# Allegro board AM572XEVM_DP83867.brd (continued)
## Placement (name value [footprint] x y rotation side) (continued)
R369  47,1%  [402]  36.18 49.88 90 bottom
R370  47,1%  [402]  35.38 46.13 270 bottom
R371  47,1%  [402]  36.98 46.13 270 bottom
R372  47,1%  [402]  40.98 46.13 270 bottom
R373  47,1%  [402]  39.38 44.28 90 bottom
R374  47,1%  [402]  39.38 46.13 270 bottom
R375  47,1%  [402]  38.58 44.28 90 bottom
R376  47,1%  [402]  37.78 49.88 90 bottom
R377  47,1%  [402]  37.78 40.53 270 bottom
R378  47,1%  [402]  38.58 46.13 270 bottom
R379  47,1%  [402]  37.78 44.28 90 bottom
R380  47,1%  [402]  36.18 44.28 90 bottom
R381  47,1%  [402]  36.18 40.53 270 bottom
R382  47,1%  [402]  35.38 44.28 90 bottom
R383  47,1%  [402]  35.38 40.53 270 bottom
R384  0,1%  [402]  24.26 105.41 270 bottom
R385  0,1%  [402]  60.45 2.29 270 bottom
R386  0,1%  [402]  91.19 2.29 270 bottom
R387  0,1%  [402]  63.75 105.41 90 bottom
R391  2.2K,1%  [402]  84.33 81.03 90 top
R392  2.2K,1%  [402]  85.22 81.03 90 top
R393  0,DNI  [402]  89.41 38.35 270 bottom
R394  0,DNI  [402]  90.3 38.35 270 bottom
R395  0,1%  [402]  69.47 53.59 0 top
R396  154K,1%  [402]  115.06 48.77 0 bottom
R397  470K,1%  [402]  115.06 47.88 0 bottom
R398  4.7K  [402]  82.17 85.6 180 top
R399  4.7K  [402]  82.17 84.58 180 top
R400  0,1%  [402]  20.57 3.3 180 bottom
R401  0,1%  [402]  116.59 3.3 0 bottom
R402  0,1%  [402]  20.32 96.27 180 bottom
R403  0,1%  [402]  121.67 89.92 90 bottom
R404  22.6K,1%  [402]  77.22 68.83 270 bottom
R405  10K,DNI  [402]  81.92 68.83 270 bottom
R407  10K,1%  [402]  29.72 105.41 90 bottom
R408  47K,1%  [402]  104.39 8.51 270 bottom
R409  620K  [402]  98.3 6.35 90 bottom
R410  330K  [402]  99.31 6.35 270 bottom
R411  10K,1%,DNI  [402]  67.94 72.77 180 bottom
R412  0,1%  [402]  96.27 8.51 90 bottom
R413  0,1%,DNI  [402]  98.3 8.51 90 bottom
R414  0,1%  [402]  97.28 8.51 270 bottom
R415  47K,1%  [402]  99.31 8.51 270 bottom
R416  0,1%  [402]  87.76 84.45 270 bottom
R417  220,5%  [402]  67.56 35.6 270 bottom
R418  499,1%  [402]  52.07 76.83 180 bottom
R419  10K,1%  [402]  55.25 76.83 0 bottom
R420  40.2K,1%  [402]  49.53 71.75 0 bottom
R421  10K,1%  [402]  73.03 68.33 0 bottom
R422  0,1%  [402]  68.99 49.91 270 bottom
R423  499,1%  [402]  80.52 70.99 0 bottom
R424  10K,1%  [402]  77.72 70.99 0 bottom
R425  40.2K,1%  [402]  81.53 75.82 180 bottom
R429  DNI  [402]  49.53 76.83 180 bottom
R430  DNI  [402]  83.06 70.99 0 bottom
R432  10K,1%,DNI  [402]  117.98 62.99 180 top
R433  10K,1%  [402]  69.85 73.28 45 bottom
R434  10K,1%,DNI  [402]  41.78 69.85 270 bottom
R437  10K,1%  [402]  107.8 54.91 270 top
R440  11K,1%  [402]  88.39 72.26 270 top
R441  11K,1%  [402]  102.16 72.54 270 top
R442  1.87K,1%  [402]  86.18 66.6 90 bottom
R451  0,1%  [402]  101.42 69.19 270 bottom
R461  2.49K,1%  [402]  107.42 62.15 180 bottom
R468  4.7K,0402  [402]  96.49 67.94 270 bottom
R469  4.7K,0402  [402]  110.11 68.24 270 bottom
R470  0,1%  [603]  97.82 61.21 90 top
R471  0,1%  [603]  87.1 73.86 270 top
R472  0,1%  [603]  85.32 73.86 270 top
R473  0,1%  [603]  111.66 74.12 270 top
R474  0,1%  [603]  111.02 60.38 90 top
R475  0,1%  [603]  109.58 74.12 270 top
R476  10K,1%  [402]  82.5 61.93 270 top
R477  0,0402  [402]  87.63 66.98 270 bottom
R478  0,0402  [402]  101.35 66.27 90 bottom
R479  0,0402  [402]  86.64 69.77 270 top
R480  0,0402  [402]  100.41 69.93 270 top
S1  SW PUSH_TH  [SW4_EVQF004R]  31.46 105.32 180 top
S2  SW PUSH_TH  [SW4_EVQF004R]  53.98 2.25 0 top
TP4  TESTPT1  [TP1-8040]  42.55 76.2 0 top
TP5  TP  [TP30C12D]  59.36 83.21 180 bottom
TP6  TP  [TP30C12D]  68.07 26.92 180 bottom
TP7  TP  [TP30C12D]  62.99 85.72 180 bottom
TP8  TP  [TP30C12D]  53.19 64.36 180 bottom
TP9  TP  [TP30C12D]  53.8 63.22 180 bottom
TP13  TP  [TP30C12D]  55.12 71.12 180 bottom
TP16  TP  [TP30C12D]  51.05 45.97 180 bottom
TP17  TP  [TP30C12D]  84.33 78.49 180 bottom
TP18  TP  [TP30C12D]  84.28 76.28 180 bottom
TP19  TP  [TP30C12D]  64.26 59.31 180 bottom
TP20  TP  [TP30C12D]  35.38 51.21 0 top
TP21  TP  [TP30C12D]  35.38 28.8 0 top
TP28  TP  [TP30C12D]  86.31 78.49 0 top
TP29  TP  [TP30C12D]  86.28 76.33 0 top
U1  TPS54531D  [DDA-8]  31.75 65.41 0 top
U2  TPS22965DSG  [WSON-8]  43.18 69.22 180 top
U3  TPS54531D  [DDA-8]  29.34 79.25 0 top
U4  TMP102AIDRLT  [SOT563]  69.34 18.41 90 top
U5  TPS6590376ZWSR  [BGA169_N13_P8]  66.59 72.41 270 top
U6  MCP79410,TFDN  [DFN8_2X3MM]  85.09 84.45 270 top
U7  CDCM9102RHBR  [QFN32]  29.21 50.8 180 top
U8  MEM_24WC256_8SOIC  [SOIC_8]  52.2 81.28 90 bottom
U9  SN74LVC1G11DBV  [SC70-6]  77.47 61.59 0 bottom
U10  SN74LVC1G08DCK  [SC70-5]  80.01 61.59 0 bottom
U11  AM572x  [SKTBGA-ZKK-6334-P760]  67.39 40.81 180 top
U12  TPS_3808G09  [SOT23-6]  58.42 8.89 270 top
U13  TPS_3808G33  [SOT23-6]  51.46 67.34 180 top
U14  DP83867IRRGZ  [QFN48_19-68_280X280_1]  91.25 66.49 270 top
U15  DP83867IRRGZ  [QFN48_19-68_280X280_1]  105 66.79 270 top
U16  TPS74801  [DRC10-11X33]  102.23 38.1 90 bottom
U17  TUSB8041  [VQFN64S9X9P5]  92.71 29.84 90 top
U18  TLV320AIC3104  [QFN32]  58.42 17.78 90 top
U19  TPS77018DBV  [SOT23-5]  58.42 12.7 270 top
U20  SN74LVC2G241  [U_8_DCU]  29.84 36.83 270 top
U21  TPD12S016 24UQFN  [QFN24S_2X4P4]  62.87 95.5 270 top
U22  MEM_MNAND_4GB  [BGA153_P14_P5_11P5X13]  92.08 43.81 180 top
U23  256MBx16 DDR3L  [BGA96_T9_P8_9X14]  41.78 56.41 270 top
U24  256MBx16 DDR3L  [BGA96_T9_P8_9X14]  41.78 45.21 270 top
U25  256MBx16 DDR3L  [BGA96_T9_P8_9X14]  41.78 22.8 270 top
U26  256MBx16 DDR3L  [BGA96_T9_P8_9X14]  41.78 34 270 top
U27  TPS51200_10SON  [DRC10-11X33]  28.58 20.95 90 top
U28  TPS54531D  [DDA-8]  102.87 43.18 0 top
U29  TPS2561DRC  [DRC10-11X33]  102.23 27.94 90 bottom
U30  TPS2561DRC  [DRC10-11X33]  102.23 33.02 90 bottom
U31  PI2DBS212_TQFN  [TQFN28S_3P5X5P5P5]  77.34 76.58 90 top
U32  TL5209  [SO8-25X75]  109.86 48.9 270 bottom
U33  SN75LVCP412A  [QFN20S4X4P5-2]  78.74 84.84 90 top
U34  SN74LVC2G132DCU  [U_8_DCU]  80.01 68.33 180 bottom
U35  TLVH431  [SOT23-3]  50.16 74.3 0 bottom
U42  SN74LVC1G06DCK  [SC70-5]  101.85 8.51 270 bottom
U43  TLVH431  [SOT23-3]  82.42 73.41 180 bottom
U44  SN74LVC1G08  [SM-SO-SC70-5]  109.32 55.42 0 top
U47  TPD1E05U06  [TPD4E05U06DQA]  93.01 74.42 180 top
U48  TPD1E05U06  [TPD4E05U06DQA]  90.02 74.42 180 top
U49  TPD1E05U06  [TPD4E05U06DQA]  106.76 74.7 180 top
U50  TPD1E05U06  [TPD4E05U06DQA]  103.76 74.7 180 top
U51  SN74LVC1G08  [SM-SO-SC70-5]  84.04 62.41 0 top
Y1  CFS-20632768DZBB  [XTAL_CFS-206]  85.09 87.12 270 bottom
Y2  20MHz,SMD  [XTAL2_6X3P5_SMD]  61.4 55.88 180 top
Y3  22.5792MHZ  [XTAL4_3P2X2P5_SMD]  68.96 55.88 0 top
Y5  25MHz  [XTAL_3P2X5SMD]  84.35 68.73 270 top
Y6  DNI  [XTAL_3P2X5SMD]  98.15 69.16 270 top
Y7  24MHz  [OSC4_87-146SMD_126X197-1]  86.61 23.62 270 bottom
Y8  25MHz,8pF  [XTAL4_3P2X2P5_SMD]  29.34 45.09 90 bottom
Y9  16.384MHz  [XTAL4_3P2X2P5_SMD]  74.55 79.88 90 bottom

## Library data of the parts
BAT1 = BATT_HOLD_BH501
C1 C7 C401 = CAP_0.1uF_X7R_25V_10% 0805
C2 C8 C9 C403 C404 C406 C411 C413 = CAP_100UF_TANT_6.3V_3528-21: Tolerance: TOL*; User Part Number: P/N*
C3 C14 C402 C438-C440 C445 = CAP_4.7uF_X5R_50V_10%_LESR_1210: Tolerance: TOL*; User Part Number: P/N*
C4 C13 C408 = CAP_8.2nF_X5R_10V_10%_0201
C5 C10 C409 = CAP
C6 C410 = CAP_6.8nF_X7R_50V_10%_0805
C11 = CAP_820PF_X5R_50V_10%_0805
C12 = CAP_15PF_NPO_50V_5%_0805
C15 C16 C30 C81 C94 C97 C99 C104 C105 C108 C110 C111 C216 C230 C231 C239 C241 C242 C244 C247 C248 C252 C253 C258 C259 C262 C264 C270 C272 C274 C334 C388 C392 C398 C399 C405 C407 C412 C414 C415 C419 C422-C428 C430 C433 C434 C441 C446-C451 = CAP_0.1uF_X7R_16V_10% 0402: signal model: CAP_0.1UF_X7R_16V_10%_0402__402_0.1uf_16V
C17-C22 C24-C29 C63 C80 C92 C246 C255 C256 C267 C496 C500 = CAP_2.2uF_X5R_6.3V_10%_0402
C23 C50 C53 C54 C113 C122 C130 C131 C189 C190 C202 C238 C249 C254 C257 C271 C295 C312 C327 C341 C350 C361 C369 C387 C389 C393-C397 C431 C432 C436 C437 C442 C481 C494 C497 = CAP_10uF_X5R_6.3V_20%_0603
C31 C32 = CAP_10PF_COG_50V_5%_0402
C33 C35 C37 C39 C41 C43 C45 C46 C48 C64 C70 C163 C179 C261 C265 C268 = CAP_4.7uF_X5R_6.3V_20%_0402
C34 C36 C38 C47 C49 C250 C251 = CAP_47uF_X5R_6.3V_20%_1206
C40 C42 C44 C583 C584 = CAP_47uF_X5R_6.3V_20% 0805
C51 C55 C57-C62 C66-C69 C71-C77 C82-C87 C95 C96 C98 C114-C121 C123-C129 C132-C140 C157-C160 C169 C170 C173-C178 C181-C188 C191-C196 C198-C201 C203 C204 C236 C243 C263 C273 C421 C470 C482-C493 C498 C499 = CAP_0.1uF_X5R_6.3V_20% 0201
C52 C56 C78 C88 C89 C161 C162 C165-C168 C171 C172 C266 C269 C275-C294 C296-C311 C313-C326 C328-C333 C335-C340 C342-C349 C351-C360 C362-C368 C370-C386 = CAP_0.22uf_X5R_6.3V_20%_0201
C65 C79 = CAP_0.47UF_X5R_4V_20%_0201
C90 C91 C141-C155 C164 C260 C471 C495 = CAP_1.0UF_X5R_4V_20%_0201
C93 C156 C180 = CAP_22uF_X5R_6.3V_20%_0805
C100-C103 = CAP_18PF_COG_50V_5%_0402
C109 C112 = CAP_220PF_X7R_50V_10%_0402
C197 C237 C245 C390 C391 C429 = CAP_0.001_X7R_50V_10%_0402
C215 = CAP_0.1uF_X7R_16V_10% 0402: User Part Number: P/N*; Tolerance: TOL*; signal model: CAP_0.1UF_X7R_16V_10%_0402__402_0.1uf_16V
C217 C218 C232 C233 = CAP_18PF_NPO_50V_5%_0402
C235 C240 = CAP_33PF_COG_50V_5%_0402
C400 = CAP_10PF_NPO_50V_5%_0402
C416-C418 C420 C454-C457 = CAP_0.1uF_X7R_16V_10% 0402: signal model: CAP_0.1UF_X7R_16V_10%_0402__4_1_0.01uf_16V
C435 = CAP_DNI_0402
C443 = CAP_470PF_X7R_25V_10%_0402
C452 C453 = C_12pF/0402/50V_COG_0402
C472-C476 C478 C586-C593 = CAP_0.1uF_X7R_16V_10% 0402
C479 = CAP_10uF_X5R_6.3V_20%_0603: Tolerance: TOL*; User Part Number: P/N*
C501 C585 = 0.01uFCapacitor16V10%0402
C510-C512 C518-C520 C522 C526 C527 C547 C549-C551 C555 C556 C560-C562 = CAP_0.1uF_X5R_16V_10% 0201
C529-C544 = CAP_4.7pF_C0G_50V_0201
C563-C580 = CAP_1uF_X6S_16V_10% 0402
D1 D2 D24 = DIO_ZEN_DDZ9678-7_1.8V
D3-D7 D41 = LED_LTST_C150GKT
D8-D11 = PROT_PESD0603_240
D12-D19 = IC_TPD1E05U06_0
D20-D23 = IC_TPD2E001DRL
D25-D33 D38 D40 = IC_TPD2EUSB30ADRTR_1: Tolerance: TOL*; User Part Number: P/N*
D34-D37 D42 = IC_TPD1E05U06
F1 = FUSE_4A_QUICK
FB9 = FERRITE_180_800_0805
FL1-FL4 = CHOKE_DLW21SN121HQ2_3: Tolerance: TOL*; User Part Number: P/N*
J1 J5 = HDR_1x1_M_.1
J3 J4 J6 = HDR_1x3_0.1
L1 L2 L16 = INDUCTOR
L3-L5 L9 = IND_PWR_1.0uH_4.2A_SMD
L6-L8 L25 L26 = IND_PWR_1.0uH_2.7A_SMD
L10-L12 L21 L22 L24 = FLT_HIFREQ_.47UF
L13-L15 L17-L20 L23 = FERRITE_220_0805: Tolerance: TOL*; User Part Number: P/N*
MH1-MH5 = TESTPOINT
P1 = CONN_PWRJack_PJ-080BH
P2 P3 = HDR_5x2_M_2.1: User Part Number: ***
P4 = HDR_JTAG_20P
P5 = CONN_RJ45_DUAL_GIGABIT_new
P6 = CONN_11P_eSATA
P7 = CONN_MINI-USB-AB_1
P8 P9 = CONN_STEREO_3.5MM_1SW
P10 = HEADER 6: User Part Number: ***
P11 = HDMI-RA-19_0: Tolerance: TOL; User Part Number: PART#
P12 = microSD_molex_104031-0811: Tolerance: X; User Part Number: X
P13 = CONN_USB3_3.0_A
P15 = CONN_USB3_3.0_A_DUAL
P16-P19 = CONN_30x2_5.27mm: Tolerance: TOL*; User Part Number: PRT#
Q3 Q4 = TRN_DMC56404
Q5 = TRN_NTA4153N
Q6 = TRN_BSS138_0
Q7 = BSS138/SOT_0: Tolerance: TOL*; User Part Number: P/N*
Q8 Q9 = TRN_1: Tolerance: TOL*; User Part Number: P/N*
R1 R7 R34-R36 = RES 0.002_1/2W_1%_0805
R2 R13 R292 = RES_10.1K_1/16W_1%_0402
R3 R5 R9 R14 R294 R296 = RESISTOR
R4 R12 R293 R295 = RES_12.1K_1/16W_1%_0402
R6 R11 R297 = RES_20.5K_1/16W_1%_0402
R8 R240 R273 R274 R303 R328 = RES_1K_1/16W_5%_0402
R10 R20-R24 R26 R27 R31 R37 R41 R42 R44 R46 R49-R52 R56 R58 R180-R183 R187 R188 R190-R197 R200 R205 R214 R236 R239 R247 R248 R260-R265 R272 R285 R287 R288 R313 R320 R321 R330 R335 R405 R407-R411 R415 R419-R421 R424 R425 R429 R430 R432-R434 R437 R476 = RES_10K_1/16W_1%_0402
R15 R33 = RES_4.75K_1/16W_1%_0402
R16 R17 R43 R212 R213 R391 R392 = RES_2.2K_1/16W_1%_0402
R18 R19 R28 R38 R40 R45 R47 R54 R55 R189 R237 R241 R242 R311 R312 R318 R319 R322 R323 = RES_DNI_1/16W_1%_0402
R29 R30 R32 R39 R53 R57 R244 R249 R290 R291 R302 R384 R395 R413 = RES_0_1/16W_1%_0402: signal model: RES_0_1/16W_1%_0402_402_0_1%_0_1%
R48 R219-R222 R286 R298 R309 R310 = RES_100K_1/16W_1%_0402
R59 R62 R66 R204 R207 R209 R215-R218 R243 R245 R246 R333 R334 R398 R399 R468 R469 = RES_4.7K_1/16W_5%_0402
R61 R63 R64 R124-R136 R138-R150 R152 R153 R223 = RES_22_1/16W_5%_0402: signal model: RES_22_1/16W_5%_0402_402_22_5%_22_5%
R68 R69 R97 R98 R396 R397 = RES_470_1/10W_5%_0402
R84-R89 R111-R115 R118 = RES_22_1/16W_5%_0402: signal model: RES_0_1/16W_1%_0402_402_0_1%_0_1%
R201 R442 = RES_1.87K_1/16W_1%_0402
R202 R299 R300 R332 R385-R387 R400-R403 = RES_1M_1/16W_1%_0402
R203 = RES_4.99K_1/16W_1%_0402
R206 = RES_9.09K_1/16W_1%_0402
R210 R211 R314 R315 = RES_27_1/16W_1%_0402
R224 R225 R227 R229 R230 R233 R289 = RES_10_1/10W_5%_0402
R226 R228 R231 R232 R234 R235 R329 = RES_20K_1/16W_1%_0402
R250-R259 = RES_47K_1/16W_1%_0402
R266-R271 = RES_33_1/16W_5%_0402
R275-R278 R418 R423 = RES_240_1/16W_1%_0402
R279-R284 = RES_49.9K_1/16W_1%_0402
R308 = RES_100_1/10W_5%_0402
R331 = RES_1M_1/16W_1%_0402: User Part Number: P/N*; Tolerance: TOL*
R336-R383 = RES_47_1/16W_1%_0402
R393 R394 R412 R414 R416 R422 R451 = RES_0_1/16W_1%_0402
R404 = RES_22.6K_1/16W_1%_0402
R417 = RES_220_1/16W_5%_0402
R440 R441 R477-R480 = RES_11K_1/16W_1%_0402
R461 = RES_2.49K_1/16W_1%_0402
R470-R475 = RES_0_1/16W_1%_0603
S1 S2 = SW PUSH_TH: Tolerance: X; User Part Number: X
TP4 = TESTPT1
TP5-TP9 TP13 TP16-TP21 TP28 TP29 = TP
U1 U3 U28 = IC_TPS54331,3A_0: Tolerance: TOL*; User Part Number: P/N*
U2 = TPS22965DSG_1
U4 = IC_TMP102AIDRL_SOT563
U5 = IC_TPS659039_8
U6 = IC_MCP79410: Tolerance: TOL*; User Part Number: P/N*
U7 = IC_CDCM9102RHBR_0
U8 = MEM_24WC256_0
U9 = IC_SN74LVC1G11_DRY
U10 = IC_SN74LVC1G08_DCK
U11 = IC_AM572x_BGA_36
U12 U13 = PWR_TPS3808G09DBVR_SOT23_0
U14 U15 = DP83867IRRGZ_VQFN48
U16 = PWR_TPS74801_SON: Tolerance: X; User Part Number: X
U17 = IC_TUSB8041_2
U18 = IC_TLV320AIC3104_5
U19 = PWR_TPS7018DBV_SOT23_5
U20 = IC_SN74LVC2G241_1
U21 = IC_TPD12S016
U22 = MEM_MNAND_1
U23-U26 = MEM_DDR3L_256MBx16_0
U27 = IC_TPS51200_10S0N: Tolerance: X; User Part Number: X
U29 U30 = PWR_TPS2560_DRC_0: Tolerance: X; User Part Number: X
U31 = IC_PI2DBS212ZHE_TQFN_9
U32 = PWR_TLV70233DBV_0: Tolerance: X; User Part Number: X
U33 = IC_SN75LVCP412A_1
U34 = IC_SN74LVC2G132DCU
U35 U43 = MA735/TO_0: Tolerance: TOL*; User Part Number: P/N*
U42 = IC_SN74LVC1G06DCK
U44 U51 = SN74LVC1G08DCKT_SC70
U47-U50 = TPD1E05U06
Y1 = CRYS_32_768KHz_SMD
Y2 = CRYS_20MHz_12.5pF_2P_3.2x1.5
Y3 = CRYS_22.5792MHz_7pF_4P_3.2x2.5
Y5 Y6 = CRYS_25MHz_18pF_2P_5.0x3.2
Y7 = CRYS_24MHz_2PIN: Tolerance: TOL*; User Part Number: P/N*
Y8 = CRYS_25MHz_8pF_4P_3.2x2.5
Y9 = CRYS_24MHz_SCC

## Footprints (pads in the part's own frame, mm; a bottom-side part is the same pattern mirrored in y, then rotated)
2XSON
  rect 0.6x0.5 smd: 1(-0.5,0) 2(0.5,0)
201
  custom 0.075x0.075 smd: 1(-0.312,0) 2(0.312,0)
402
  rect 0.45x0.5 smd: 1(-0.475,0) 2(0.475,0)
603
  rect 0.889x0.813 smd: 1(-0.762,0) 2(0.762,0)
805
  rect 1.143x1.27 smd: 1(-0.889,0) 2(0.889,0)
1206
  rect 1.397x1.651 smd: 1(-1.397,0) 2(1.397,0)
1210
  rect 1.6x2.667 smd: 1(-1.397,0) 2(1.397,0)
1812
  rect 1.2x3.3 smd: 1(-1.95,0) 2(1.95,0)
6032
  rect 2.54x2.286 smd: 1(-2.499,0) 2(2.499,0)
BATT2_78X492
  round 1.524 hole 0.965: 1(-2.54,-1.143) 2(2.54,1.143)
BGA96_T9_P8_9X14
  round 0.356 smd: A1(-3.2,6.001) A2(-2.4,6.001) A3(-1.6,6.001) A7(1.6,6.001) A8(2.4,6.001) A9(3.2,6.001) B1(-3.2,5.201) B2(-2.4,5.201) B3(-1.6,5.201) B7(1.6,5.201) B8(2.4,5.201) B9(3.2,5.201) C1(-3.2,4.401) C2(-2.4,4.401) C3(-1.6,4.401) C7(1.6,4.401) C8(2.4,4.401) C9(3.2,4.401) D1(-3.2,3.6) D2(-2.4,3.6) D3(-1.6,3.6) D7(1.6,3.6) D8(2.4,3.6) D9(3.2,3.6) E1(-3.2,2.8) E2(-2.4,2.8) E3(-1.6,2.8) E7(1.6,2.8) E8(2.4,2.8) E9(3.2,2.8) F1(-3.2,2) F2(-2.4,2) F3(-1.6,2) F7(1.6,2) F8(2.4,2) F9(3.2,2) G1(-3.2,1.2) G2(-2.4,1.2) G3(-1.6,1.2) G7(1.6,1.2) G8(2.4,1.2) G9(3.2,1.2) H1(-3.2,0.4) H2(-2.4,0.4) H3(-1.6,0.4) H7(1.6,0.4) H8(2.4,0.4) H9(3.2,0.4) J1(-3.2,-0.4) J2(-2.4,-0.4) J3(-1.6,-0.4) J7(1.6,-0.4) J8(2.4,-0.4) J9(3.2,-0.4) K1(-3.2,-1.2) K2(-2.4,-1.2) K3(-1.6,-1.2) K7(1.6,-1.2) K8(2.4,-1.2) K9(3.2,-1.2) L1(-3.2,-2) L2(-2.4,-2) L3(-1.6,-2) L7(1.6,-2) L8(2.4,-2) L9(3.2,-2) M1(-3.2,-2.8) M2(-2.4,-2.8) M3(-1.6,-2.8) M7(1.6,-2.8) M8(2.4,-2.8) M9(3.2,-2.8) N1(-3.2,-3.6) N2(-2.4,-3.6) N3(-1.6,-3.6) N7(1.6,-3.6) N8(2.4,-3.6) N9(3.2,-3.6) P1(-3.2,-4.401) P2(-2.4,-4.401) P3(-1.6,-4.401) P7(1.6,-4.401) P8(2.4,-4.401) P9(3.2,-4.401) R1(-3.2,-5.201) R2(-2.4,-5.201) R3(-1.6,-5.201) R7(1.6,-5.201) R8(2.4,-5.201) R9(3.2,-5.201) T1(-3.2,-6.001) T2(-2.4,-6.001) T3(-1.6,-6.001) T7(1.6,-6.001) T8(2.4,-6.001) T9(3.2,-6.001)
BGA153_P14_P5_11P5X13
  round 0.254 smd: A1(-3.25,3.25) A2(-2.75,3.25) A3(-2.25,3.25) A4(-1.75,3.25) A5(-1.25,3.25) A6(-0.75,3.25) A7(-0.25,3.25) A8(0.25,3.25) A9(0.75,3.25) A10(1.25,3.25) A11(1.75,3.25) A12(2.25,3.25) A13(2.75,3.25) A14(3.25,3.25) B1(-3.25,2.75) B2(-2.75,2.75) B3(-2.25,2.75) B4(-1.75,2.75) B5(-1.25,2.75) B6(-0.75,2.75) B7(-0.25,2.75) B8(0.25,2.75) B9(0.75,2.75) B10(1.25,2.75) B11(1.75,2.75) B12(2.25,2.75) B13(2.75,2.75) B14(3.25,2.75) C1(-3.25,2.25) C2(-2.75,2.25) C3(-2.25,2.25) C4(-1.75,2.25) C5(-1.25,2.25) C6(-0.75,2.25) C7(-0.25,2.25) C8(0.25,2.25) C9(0.75,2.25) C10(1.25,2.25) C11(1.75,2.25) C12(2.25,2.25) C13(2.75,2.25) C14(3.25,2.25) D1(-3.25,1.75) D2(-2.75,1.75) D3(-2.25,1.75) D4(-1.75,1.75) D12(2.25,1.75) D13(2.75,1.75) D14(3.25,1.75) E1(-3.25,1.25) E2(-2.75,1.25) E3(-2.25,1.25) E5(-1.25,1.25) E6(-0.75,1.25) E7(-0.25,1.25) E8(0.25,1.25) E9(0.75,1.25) E10(1.25,1.25) E12(2.25,1.25) E13(2.75,1.25) E14(3.25,1.25) F1(-3.25,0.75) F2(-2.75,0.75) F3(-2.25,0.75) F5(-1.25,0.75) F10(1.25,0.75) F12(2.25,0.75) F13(2.75,0.75) F14(3.25,0.75) G1(-3.25,0.25) G2(-2.75,0.25) G3(-2.25,0.25) G5(-1.25,0.25) G10(1.25,0.25) G12(2.25,0.25) G13(2.75,0.25) G14(3.25,0.25) H1(-3.25,-0.25) H2(-2.75,-0.25) H3(-2.25,-0.25) H5(-1.25,-0.25) H10(1.25,-0.25) H12(2.25,-0.25) H13(2.75,-0.25) H14(3.25,-0.25) J1(-3.25,-0.75) J2(-2.75,-0.75) J3(-2.25,-0.75) J5(-1.25,-0.75) J10(1.25,-0.75) J12(2.25,-0.75) J13(2.75,-0.75) J14(3.25,-0.75) K1(-3.25,-1.25) K2(-2.75,-1.25) K3(-2.25,-1.25) K5(-1.25,-1.25) K6(-0.75,-1.25) K7(-0.25,-1.25) K8(0.25,-1.25) K9(0.75,-1.25) K10(1.25,-1.25) K12(2.25,-1.25) K13(2.75,-1.25) K14(3.25,-1.25) L1(-3.25,-1.75) L2(-2.75,-1.75) L3(-2.25,-1.75) L12(2.25,-1.75) L13(2.75,-1.75) L14(3.25,-1.75) M1(-3.25,-2.25) M2(-2.75,-2.25) M3(-2.25,-2.25) M4(-1.75,-2.25) M5(-1.25,-2.25) M6(-0.75,-2.25) M7(-0.25,-2.25) M8(0.25,-2.25) M9(0.75,-2.25) M10(1.25,-2.25) M11(1.75,-2.25) M12(2.25,-2.25) M13(2.75,-2.25) M14(3.25,-2.25) N1(-3.25,-2.75) N2(-2.75,-2.75) N3(-2.25,-2.75) N4(-1.75,-2.75) N5(-1.25,-2.75) N6(-0.75,-2.75) N7(-0.25,-2.75) N8(0.25,-2.75) N9(0.75,-2.75) N10(1.25,-2.75) N11(1.75,-2.75) N12(2.25,-2.75) N13(2.75,-2.75) N14(3.25,-2.75) P1(-3.25,-3.25) P2(-2.75,-3.25) P3(-2.25,-3.25) P4(-1.75,-3.25) P5(-1.25,-3.25) P6(-0.75,-3.25) P7(-0.25,-3.25) P8(0.25,-3.25) P9(0.75,-3.25) P10(1.25,-3.25) P11(1.75,-3.25) P12(2.25,-3.25) P13(2.75,-3.25) P14(3.25,-3.25)
BGA169_N13_P8
  round 0.356 smd: A1(-4.8,4.8) A2(-4,4.8) A3(-3.2,4.8) A4(-2.4,4.8) A5(-1.6,4.8) A6(-0.8,4.8) A7(0,4.8) A8(0.8,4.8) A9(1.6,4.8) A10(2.4,4.8) A11(3.2,4.8) A12(4,4.8) A13(4.8,4.8) B1(-4.8,4) B2(-4,4) B3(-3.2,4) B4(-2.4,4) B5(-1.6,4) B6(-0.8,4) B7(0,4) B8(0.8,4) B9(1.6,4) B10(2.4,4) B11(3.2,4) B12(4,4) B13(4.8,4) C1(-4.8,3.2) C2(-4,3.2) C3(-3.2,3.2) C4(-2.4,3.2) C5(-1.6,3.2) C6(-0.8,3.2) C7(0,3.2) C8(0.8,3.2) C9(1.6,3.2) C10(2.4,3.2) C11(3.2,3.2) C12(4,3.2) C13(4.8,3.2) D1(-4.8,2.4) D2(-4,2.4) D3(-3.2,2.4) D4(-2.4,2.4) D5(-1.6,2.4) D6(-0.8,2.4) D7(0,2.4) D8(0.8,2.4) D9(1.6,2.4) D10(2.4,2.4) D11(3.2,2.4) D12(4,2.4) D13(4.8,2.4) E1(-4.8,1.6) E2(-4,1.6) E3(-3.2,1.6) E4(-2.4,1.6) E5(-1.6,1.6) E6(-0.8,1.6) E7(0,1.6) E8(0.8,1.6) E9(1.6,1.6) E10(2.4,1.6) E11(3.2,1.6) E12(4,1.6) E13(4.8,1.6) F1(-4.8,0.8) F2(-4,0.8) F3(-3.2,0.8) F4(-2.4,0.8) F5(-1.6,0.8) F6(-0.8,0.8) F7(0,0.8) F8(0.8,0.8) F9(1.6,0.8) F10(2.4,0.8) F11(3.2,0.8) F12(4,0.8) F13(4.8,0.8) G1(-4.8,0) G2(-4,0) G3(-3.2,0) G4(-2.4,0) G5(-1.6,0) G6(-0.8,0) G7(0,0) G8(0.8,0) G9(1.6,0) G10(2.4,0) G11(3.2,0) G12(4,0) G13(4.8,0) H1(-4.8,-0.8) H2(-4,-0.8) H3(-3.2,-0.8) H4(-2.4,-0.8) H5(-1.6,-0.8) H6(-0.8,-0.8) H7(0,-0.8) H8(0.8,-0.8) H9(1.6,-0.8) H10(2.4,-0.8) H11(3.2,-0.8) H12(4,-0.8) H13(4.8,-0.8) J1(-4.8,-1.6) J2(-4,-1.6) J3(-3.2,-1.6) J4(-2.4,-1.6) J5(-1.6,-1.6) J6(-0.8,-1.6) J7(0,-1.6) J8(0.8,-1.6) J9(1.6,-1.6) J10(2.4,-1.6) J11(3.2,-1.6) J12(4,-1.6) J13(4.8,-1.6) K1(-4.8,-2.4) K2(-4,-2.4) K3(-3.2,-2.4) K4(-2.4,-2.4) K5(-1.6,-2.4) K6(-0.8,-2.4) K7(0,-2.4) K8(0.8,-2.4) K9(1.6,-2.4) K10(2.4,-2.4) K11(3.2,-2.4) K12(4,-2.4) K13(4.8,-2.4) L1(-4.8,-3.2) L2(-4,-3.2) L3(-3.2,-3.2) L4(-2.4,-3.2) L5(-1.6,-3.2) L6(-0.8,-3.2) L7(0,-3.2) L8(0.8,-3.2) L9(1.6,-3.2) L10(2.4,-3.2) L11(3.2,-3.2) L12(4,-3.2) L13(4.8,-3.2) M1(-4.8,-4) M2(-4,-4) M3(-3.2,-4) M4(-2.4,-4) M5(-1.6,-4) M6(-0.8,-4) M7(0,-4) M8(0.8,-4) M9(1.6,-4) M10(2.4,-4) M11(3.2,-4) M12(4,-4) M13(4.8,-4) N1(-4.8,-4.8) N2(-4,-4.8) N3(-3.2,-4.8) N4(-2.4,-4.8) N5(-1.6,-4.8) N6(-0.8,-4.8) N7(0,-4.8) N8(0.8,-4.8) N9(1.6,-4.8) N10(2.4,-4.8) N11(3.2,-4.8) N12(4,-4.8) N13(4.8,-4.8)
CHOKE4_0805-2
  rect 0.65x0.5 smd: 1(-0.8,-0.4) 2(0.8,-0.4) 3(0.8,0.4) 4(-0.8,0.4)
CNPJ-080BH
  round 1.6 hole 1.6 unplated: (0,-11.65)
  rect 2.54x2.54 hole 1.905: 1(0,0)
  oval 2.845x1.448 hole 2.21x0.813: 2(0,-6.65)
  oval 1.448x2.642 hole 0.813x2.007: SHLD1(-5.95,-5.5) SHLD2(5.95,-5.5) SHLD3(-5.95,-10.7) SHLD4(5.95,-10.7)
CON2_49LS
  rect 1.016x1.016 hole 0.508: 1(0,0)
  round 1.016 hole 0.508: 2(0,-1.245)
DDA-8
  rect 2.032x0.635 smd: 1(-2.794,1.905) 2(-2.794,0.635) 3(-2.794,-0.635) 4(-2.794,-1.905) 5(2.794,-1.905) 6(2.794,-0.635) 7(2.794,0.635) 8(2.794,1.905)
  rect 2.362x3.048 smd: 9(0,0)
DFN8_2X3MM
  rect 1.36x1.46 smd: (0,0)
  rect 0.75x0.3 smd: 1(-1.5,0.75) 2(-1.5,0.25) 3(-1.5,-0.25) 4(-1.5,-0.75) 5(1.5,-0.75) 6(1.5,-0.25) 7(1.5,0.25) 8(1.5,0.75)
DO221AC
  rect 1.194x1.499 smd: 1(-2.159,0) 2(2.159,0)
DRC10-11X33
  rect 0.305x0.762 smd: 1(-1.001,-1.473) 2(-0.5,-1.473) 3(0,-1.473) 4(0.5,-1.473) 5(1.001,-1.473) 6(1.001,1.473) 7(0.5,1.473) 8(0,1.473) 9(-0.5,1.473) 10(-1.001,1.473)
  custom 0.406x0.406 smd: 11(0,0)
ESATA-USB_COMBO_RA
  round 1.702 hole 1.702 unplated: (2.13,7.2) (2.13,-7.2)
  round 1.397 hole 0.914: 1(1.905,-3.5) 2(1.905,-1) 3(1.905,1) 4(1.905,3.5)
  oval 1.143x1.016 hole 0.787: 5(0,3.81) 6(0,2.54) 7(0,1.27) 8(0,0) 9(0,-1.27) 10(0,-2.54) 11(0,-3.81)
  oval 2.54x1.524 hole 1.6x0.635: 14(7.73,-9.2) 15(0.53,-9.2) 16(0.53,9.2) 17(7.73,9.2)
FLT3SMD_0805-2
  rect 0.6x0.8 smd: 1(-1,0) 3(1,0)
  rect 0.6x1.9 smd: 2(0,0)
FU250_200X400SMD
  rect 4.318x3.81 smd: 1(-3.188,0) 2(3.188,0)
HDMI-SMT-W-FLANGE
  rect 0.279x1.905 smd: 1(4.75,0) 2(4.249,0) 3(3.749,0) 4(3.249,0) 5(2.748,0) 6(2.248,0) 7(1.748,0) 8(1.247,0) 9(0.747,0) 10(0.246,0) 11(-0.254,0) 12(-0.754,0) 13(-1.255,0) 14(-1.755,0) 15(-2.256,0) 16(-2.756,0) 17(-3.256,0) 18(-3.757,0) 19(-4.257,0)
  oval 1.524x2.286 hole 0.787x1.499: MTG1(-7.239,-1.001) MTG2(7.239,-1.001) MTG3(-7.849,-5.9) MTG4(7.849,-5.9)
HDR2X30SMD_FX18-60P-0P8SV
  round 1.143 hole 1.143 unplated: (-16.325,-2.55) (16.325,2.55)
  rect 0.4x2.1 smd: 1(-11.6,-3.15) 2(-10.8,-3.15) 3(-10,-3.15) 4(-9.2,-3.15) 5(-8.4,-3.15) 6(-7.6,-3.15) 7(-6.8,-3.15) 8(-6,-3.15) 9(-5.2,-3.15) 10(-4.4,-3.15) 11(-3.6,-3.15) 12(-2.8,-3.15) 13(-2,-3.15) 14(-1.2,-3.15) 15(-0.4,-3.15) 16(0.4,-3.15) 17(1.2,-3.15) 18(2,-3.15) 19(2.8,-3.15) 20(3.6,-3.15) 21(4.4,-3.15) 22(5.2,-3.15) 23(6,-3.15) 24(6.8,-3.15) 25(7.6,-3.15) 26(8.4,-3.15) 27(9.2,-3.15) 28(10,-3.15) 29(10.8,-3.15) 30(11.6,-3.15) 31(-11.6,3.15) 32(-10.8,3.15) 33(-10,3.15) 34(-9.2,3.15) 35(-8.4,3.15) 36(-7.6,3.15) 37(-6.8,3.15) 38(-6,3.15) 39(-5.2,3.15) 40(-4.4,3.15) 41(-3.6,3.15) 42(-2.8,3.15) 43(-2,3.15) 44(-1.2,3.15) 45(-0.4,3.15) 46(0.4,3.15) 47(1.2,3.15) 48(2,3.15) 49(2.8,3.15) 50(3.6,3.15) 51(4.4,3.15) 52(5.2,3.15) 53(6,3.15) 54(6.8,3.15) 55(7.6,3.15) 56(8.4,3.15) 57(9.2,3.15) 58(10,3.15) 59(10.8,3.15) 60(11.6,3.15)
  oval 2x3 hole 1x1.8: A2(-16.325,2.55) B1(-13.2,0) B2(13.2,0)
  oval 2x2.4 hole 1x1.2: A3(16.325,-2.55)
HEADER10X2_SMD
  rect 0.711x2.794 smd: 1(-5.715,-2.705) 2(-5.715,2.705) 3(-4.445,-2.705) 4(-4.445,2.705) 5(-3.175,-2.705) 6(-3.175,2.705) 7(-1.905,-2.705) 8(-1.905,2.705) 9(-0.635,-2.705) 10(-0.635,2.705) 11(0.635,-2.705) 12(0.635,2.705) 13(1.905,-2.705) 14(1.905,2.705) 15(3.175,-2.705) 16(3.175,2.705) 17(4.445,-2.705) 18(4.445,2.705) 19(5.715,-2.705) 20(5.715,2.705)
IND130_160X175
  rect 1.651x2.413 smd: 1(-1.651,0) 2(1.651,0)
IND130_208X216
  rect 1.168x4.343 smd: 1(-1.651,0) 2(1.651,0)
IND_0805
  rect 1.27x1.524 smd: 1(-0.97,0) 2(0.97,0)
IND_1008
  rect 0.8x2 smd: 1(-1,0) 2(1,0)
JACK5-472X551-SJ1-3524NG
  round 2.032 hole 1.321: (-2.5,5) (-2.5,-5) (0,5) (0,-5) (5,0)
  oval 2.286x1.524 hole 1.499x0.787: (5,2.5) 2(5,-5) 3(5,5) 4(5,-2.5)
  oval 1.524x2.286 hole 0.787x1.499: 1(0,0)
LED_603
  rect 0.889x0.813 smd: 1(-0.762,0) 2(0.762,0)
MOLEX_104031-0811
  rect 0.75x1.1 smd: 1(3.105,-5.412) 2(2.005,-5.412) 3(0.905,-5.412) 4(-0.195,-5.412) 5(-1.295,-5.412) 6(-2.395,-5.412) 7(-3.495,-5.412) 8(-4.595,-5.412)
  rect 1.2x1 smd: 9(5.748,0.738) 10(5.748,4.438)
  rect 1.55x1.35 smd: 11(5.573,-5.28)
  rect 1.17x1.8 smd: 12(-5.805,-5.062)
  rect 1.9x1.35 smd: 13(-3.722,5.413) 14(2.248,5.413)
MTGH200C102D_PL
  round 4.318 hole 2.591: 1(0,0)
MTGH250C125D_PL
  round 6.35 hole 3.175: 1(0,0)
OSC4_87-146SMD_126X197-1
  rect 1.524x1.27 smd: (-1.854,1.105) (1.854,-1.105) 1(-1.854,-1.105) 2(1.854,1.105)
QFN20S4X4P5-2
  custom 0.058x0.058 smd: 1(-1.9,1) 2(-1.9,0.5) 3(-1.9,0) 4(-1.9,-0.5) 5(-1.9,-1) 6(-1,-1.9) 7(-0.5,-1.9) 8(0,-1.9) 9(0.5,-1.9) 10(1,-1.9) 11(1.9,-1) 12(1.9,-0.5) 13(1.9,0) 14(1.9,0.5) 15(1.9,1) 16(1,1.9) 17(0.5,1.9) 18(0,1.9) 19(-0.5,1.9) 20(-1,1.9)
  rect 2.159x2.159 smd: 21(0,0)
QFN24S_2X4P4
  rect 0.95x0.2 smd: 1(-0.975,1.8) 2(-0.975,1.4) 3(-0.975,1) 4(-0.975,0.6) 5(-0.975,0.2) 6(-0.975,-0.2) 7(-0.975,-0.6) 8(-0.975,-1) 9(-0.975,-1.4) 10(-0.975,-1.8) 13(0.975,-1.8) 14(0.975,-1.4) 15(0.975,-1) 16(0.975,-0.6) 17(0.975,-0.2) 18(0.975,0.2) 19(0.975,0.6) 20(0.975,1) 21(0.975,1.4) 22(0.975,1.8)
  rect 0.2x0.95 smd: 11(-0.2,-1.975) 12(0.2,-1.975) 23(0.2,1.975) 24(-0.2,1.975)
QFN32
  custom 0.058x0.058 smd: 1(-1.75,-2.475) 2(-1.25,-2.475) 3(-0.75,-2.475) 4(-0.25,-2.475) 5(0.25,-2.475) 6(0.75,-2.475) 7(1.25,-2.475) 8(1.75,-2.475) 9(2.475,-1.75) 10(2.475,-1.25) 11(2.475,-0.75) 12(2.475,-0.25) 13(2.475,0.25) 14(2.475,0.75) 15(2.475,1.25) 16(2.475,1.75) 17(1.75,2.475) 18(1.25,2.475) 19(0.75,2.475) 20(0.25,2.475) 21(-0.25,2.475) 22(-0.75,2.475) 23(-1.25,2.475) 24(-1.75,2.475) 25(-2.475,1.75) 26(-2.475,1.25) 27(-2.475,0.75) 28(-2.475,0.25) 29(-2.475,-0.25) 30(-2.475,-0.75) 31(-2.475,-1.25) 32(-2.475,-1.75)
  rect 3.454x3.454 smd: 33(0,0)
QFN48_19-68_280X280_1
  rect 0.813x0.305 smd: 1(-3.5,2.75) 2(-3.5,2.25) 3(-3.5,1.75) 4(-3.5,1.25) 5(-3.5,0.75) 6(-3.5,0.25) 7(-3.5,-0.25) 8(-3.5,-0.75) 9(-3.5,-1.25) 10(-3.5,-1.75) 11(-3.5,-2.25) 12(-3.5,-2.75) 25(3.5,-2.75) 26(3.5,-2.25) 27(3.5,-1.75) 28(3.5,-1.25) 29(3.5,-0.75) 30(3.5,-0.25) 31(3.5,0.25) 32(3.5,0.75) 33(3.5,1.25) 34(3.5,1.75) 35(3.5,2.25) 36(3.5,2.75)
  rect 0.305x0.813 smd: 13(-2.75,-3.5) 14(-2.25,-3.5) 15(-1.75,-3.5) 16(-1.25,-3.5) 17(-0.75,-3.5) 18(-0.25,-3.5) 19(0.25,-3.5) 20(0.75,-3.5) 21(1.25,-3.5) 22(1.75,-3.5) 23(2.25,-3.5) 24(2.75,-3.5) 37(2.75,3.5) 38(2.25,3.5) 39(1.75,3.5) 40(1.25,3.5) 41(0.75,3.5) 42(0.25,3.5) 43(-0.25,3.5) 44(-0.75,3.5) 45(-1.25,3.5) 46(-1.75,3.5) 47(-2.25,3.5) 48(-2.75,3.5)
  rect 5.639x5.639 smd: 49(0,0)
RJ45_2X1_XFRM_LED_NEW
  round 3.251 hole 3.251 unplated: (-6.553,-22.022) (6.553,-22.022)
  round 1.27 hole 0.889: 1(-6.02,-16.764) 2(-4.013,-16.764) 3(-2.007,-16.764) 4(0,-16.764) 5(2.007,-16.764) 6(4.013,-16.764) 7(6.02,-16.764) 8(-5.016,-14.224) 9(-3.01,-14.224) 10(-1.003,-14.224) 11(1.003,-14.224) 12(3.01,-14.224) 13(5.016,-14.224) 14(-6.02,-6.35) 15(-4.013,-6.35) 16(-2.007,-6.35) 17(0,-6.35) 18(2.007,-6.35) 19(4.013,-6.35) 20(6.02,-6.35) 21(-5.016,-3.81) 22(-3.01,-3.81) 23(-1.003,-3.81) 24(1.003,-3.81) 25(3.01,-3.81) 26(5.016,-3.81)
  round 1.397 hole 1.016: 27(-5.944,-24.867) 28(-3.912,-24.867) 29(3.912,-24.867) 30(5.944,-24.867) 31(-5.461,0) 32(-2.921,0) 33(2.921,0) 34(5.461,0)
  round 2.159 hole 1.575: SHLD1(-8.395,-26.594) SHLD2(8.395,-26.594) SHLD3(-8.395,-10.236) SHLD4(8.395,-10.236)
SC70
  rect 0.965x0.813 smd: 1(0,0) 2(0,-1.321) 3(1.778,-0.66)
SC70-5
  rect 0.406x0.762 smd: 1(-0.648,-0.953) 2(0,-0.953) 3(0.648,-0.953) 4(0.648,0.953) 5(-0.648,0.953)
SC70-6
  rect 0.406x0.762 smd: 1(-0.648,-0.953) 2(0,-0.953) 3(0.648,-0.953) 4(0.648,0.953) 5(0,0.953) 6(-0.648,0.953)
SC75
  rect 0.508x0.356 smd: 1(-0.647,0.5) 2(-0.647,-0.5) 3(0.647,0)
SIP2
  rect 1.524x1.524 hole 0.965: 1(0,0)
  round 1.524 hole 0.965: 2(0,-2.54)
SIP3
  rect 1.524x1.524 hole 0.965: 1(0,0)
  round 1.524 hole 0.965: 2(0,-2.54) 3(0,-5.08)
SIP6
  rect 1.524x1.524 hole 0.965: 1(0,0)
  round 1.524 hole 0.965: 2(0,-2.54) 3(0,-5.08) 4(0,-7.62) 5(0,-10.16) 6(0,-12.7)
SKTBGA-ZKK-6334-P760
  round 0.356 smd: A1(-10.8,10.8) A2(-10,10.8) A3(-9.2,10.8) A4(-8.4,10.8) A5(-7.6,10.8) A6(-6.8,10.8) A7(-6,10.8) A8(-5.2,10.8) A9(-4.4,10.8) A10(-3.6,10.8) A11(-2.8,10.8) A12(-2,10.8) A13(-1.2,10.8) A14(-0.4,10.8) A15(0.4,10.8) A16(1.2,10.8) A17(2,10.8) A18(2.8,10.8) A19(3.6,10.8) A20(4.4,10.8) A21(5.2,10.8) A22(6,10.8) A23(6.8,10.8) A24(7.6,10.8) A25(8.4,10.8) A26(9.2,10.8) A27(10,10.8) A28(10.8,10.8) AA1(-10.8,-5.2) AA2(-10,-5.2) AA3(-9.2,-5.2) AA4(-8.4,-5.2) AA5(-7.6,-5.2) AA6(-6.8,-5.2) AA7(-6,-5.2) AA8(-5.2,-5.2) AA9(-4.4,-5.2) AA10(-3.6,-5.2) AA11(-2.8,-5.2) AA12(-2,-5.2) AA13(-1.2,-5.2) AA14(-0.4,-5.2) AA15(0.4,-5.2) AA16(1.2,-5.2) AA17(2,-5.2) AA18(2.8,-5.2) AA19(3.6,-5.2) AA20(4.4,-5.2) AA21(5.2,-5.2) AA22(6,-5.2) AA23(6.8,-5.2) AA24(7.6,-5.2) AA25(8.4,-5.2) AA26(9.2,-5.2) AA27(10,-5.2) AA28(10.8,-5.2) AB1(-10.8,-6) AB2(-10,-6) AB3(-9.2,-6) AB4(-8.4,-6) AB5(-7.6,-6) AB6(-6.8,-6) AB7(-6,-6) AB8(-5.2,-6) AB9(-4.4,-6) AB10(-3.6,-6) AB11(-2.8,-6) AB12(-2,-6) AB13(-1.2,-6) AB14(-0.4,-6) AB15(0.4,-6) AB16(1.2,-6) AB17(2,-6) AB18(2.8,-6) AB19(3.6,-6) AB20(4.4,-6) AB21(5.2,-6) AB22(6,-6) AB23(6.8,-6) AB24(7.6,-6) AB25(8.4,-6) AB27(10,-6) AB28(10.8,-6) AC1(-10.8,-6.8) AC2(-10,-6.8) AC3(-9.2,-6.8) AC4(-8.4,-6.8) AC5(-7.6,-6.8) AC6(-6.8,-6.8) AC7(-6,-6.8) AC8(-5.2,-6.8) AC9(-4.4,-6.8) AC10(-3.6,-6.8) AC11(-2.8,-6.8) AC12(-2,-6.8) AC13(-1.2,-6.8) AC14(-0.4,-6.8) AC15(0.4,-6.8) AC16(1.2,-6.8) AC17(2,-6.8) AC18(2.8,-6.8) AC19(3.6,-6.8) AC20(4.4,-6.8) AC21(5.2,-6.8) AC22(6,-6.8) AC23(6.8,-6.8) AC24(7.6,-6.8) AC25(8.4,-6.8) AC26(9.2,-6.8) AC27(10,-6.8) AC28(10.8,-6.8) AD1(-10.8,-7.6) AD2(-10,-7.6) AD3(-9.2,-7.6) AD4(-8.4,-7.6) AD5(-7.6,-7.6) AD6(-6.8,-7.6) AD7(-6,-7.6) AD8(-5.2,-7.6) AD9(-4.4,-7.6) AD10(-3.6,-7.6) AD11(-2.8,-7.6) AD12(-2,-7.6) AD13(-1.2,-7.6) AD14(-0.4,-7.6) AD15(0.4,-7.6) AD16(1.2,-7.6) AD17(2,-7.6) AD18(2.8,-7.6) AD19(3.6,-7.6) AD20(4.4,-7.6) AD21(5.2,-7.6) AD22(6,-7.6) AD23(6.8,-7.6) AD24(7.6,-7.6) AD25(8.4,-7.6) AD26(9.2,-7.6) AD27(10,-7.6) AD28(10.8,-7.6) AE1(-10.8,-8.4) AE2(-10,-8.4) AE3(-9.2,-8.4) AE5(-7.6,-8.4) AE6(-6.8,-8.4) AE7(-6,-8.4) AE8(-5.2,-8.4) AE9(-4.4,-8.4) AE10(-3.6,-8.4) AE11(-2.8,-8.4) AE12(-2,-8.4) AE13(-1.2,-8.4) AE14(-0.4,-8.4) AE15(0.4,-8.4) AE16(1.2,-8.4) AE17(2,-8.4) AE18(2.8,-8.4) AE19(3.6,-8.4) AE20(4.4,-8.4) AE21(5.2,-8.4) AE22(6,-8.4) AE23(6.8,-8.4) AE24(7.6,-8.4) AE26(9.2,-8.4) AE27(10,-8.4) AE28(10.8,-8.4) AF1(-10.8,-9.2) AF2(-10,-9.2) AF3(-9.2,-9.2) AF4(-8.4,-9.2) AF5(-7.6,-9.2) AF6(-6.8,-9.2) AF8(-5.2,-9.2) AF9(-4.4,-9.2) AF11(-2.8,-9.2) AF12(-2,-9.2) AF14(-0.4,-9.2) AF15(0.4,-9.2) AF17(2,-9.2) AF18(2.8,-9.2) AF20(4.4,-9.2) AF21(5.2,-9.2) AF22(6,-9.2) AF23(6.8,-9.2) AF24(7.6,-9.2) AF25(8.4,-9.2) AF26(9.2,-9.2) AF27(10,-9.2) AF28(10.8,-9.2) AG1(-10.8,-10) AG2(-10,-10) AG3(-9.2,-10) AG4(-8.4,-10) AG5(-7.6,-10) AG6(-6.8,-10) AG7(-6,-10) AG8(-5.2,-10) AG9(-4.4,-10) AG10(-3.6,-10) AG11(-2.8,-10) AG12(-2,-10) AG13(-1.2,-10) AG14(-0.4,-10) AG15(0.4,-10) AG16(1.2,-10) AG17(2,-10) AG18(2.8,-10) AG19(3.6,-10) AG20(4.4,-10) AG21(5.2,-10) AG22(6,-10) AG23(6.8,-10) AG24(7.6,-10) AG25(8.4,-10) AG26(9.2,-10) AG27(10,-10) AG28(10.8,-10) AH1(-10.8,-10.8) AH2(-10,-10.8) AH3(-9.2,-10.8) AH4(-8.4,-10.8) AH5(-7.6,-10.8) AH6(-6.8,-10.8) AH7(-6,-10.8) AH8(-5.2,-10.8) AH9(-4.4,-10.8) AH10(-3.6,-10.8) AH11(-2.8,-10.8) AH12(-2,-10.8) AH13(-1.2,-10.8) AH14(-0.4,-10.8) AH15(0.4,-10.8) AH16(1.2,-10.8) AH17(2,-10.8) AH18(2.8,-10.8) AH19(3.6,-10.8) AH20(4.4,-10.8) AH21(5.2,-10.8) AH22(6,-10.8) AH23(6.8,-10.8) AH24(7.6,-10.8) AH25(8.4,-10.8) AH26(9.2,-10.8) AH27(10,-10.8) AH28(10.8,-10.8) B1(-10.8,10) B2(-10,10) B3(-9.2,10) B4(-8.4,10) B5(-7.6,10) B6(-6.8,10) B7(-6,10) B8(-5.2,10) B9(-4.4,10) B10(-3.6,10) B11(-2.8,10) B12(-2,10) B13(-1.2,10) B14(-0.4,10) B15(0.4,10) B16(1.2,10) B17(2,10) B18(2.8,10) B19(3.6,10) B20(4.4,10) B21(5.2,10) B22(6,10) B23(6.8,10) B24(7.6,10) B25(8.4,10) B26(9.2,10) B27(10,10) B28(10.8,10) C1(-10.8,9.2) C2(-10,9.2) C3(-9.2,9.2) C4(-8.4,9.2) C5(-7.6,9.2) C6(-6.8,9.2) C7(-6,9.2) C8(-5.2,9.2) C9(-4.4,9.2) C11(-2.8,9.2) C12(-2,9.2) C14(-0.4,9.2) C15(0.4,9.2) C17(2,9.2) C18(2.8,9.2) C20(4.4,9.2) C21(5.2,9.2) C23(6.8,9.2) C24(7.6,9.2) C25(8.4,9.2) C26(9.2,9.2) C27(10,9.2) C28(10.8,9.2) D1(-10.8,8.4) D2(-10,8.4) D3(-9.2,8.4) D5(-7.6,8.4) D6(-6.8,8.4) D7(-6,8.4) D8(-5.2,8.4) D9(-4.4,8.4) D10(-3.6,8.4) D11(-2.8,8.4) D12(-2,8.4) D13(-1.2,8.4) D14(-0.4,8.4) D15(0.4,8.4) D16(1.2,8.4) D17(2,8.4) D18(2.8,8.4) D19(3.6,8.4) D20(4.4,8.4) D21(5.2,8.4) D22(6,8.4) D23(6.8,8.4) D24(7.6,8.4) D26(9.2,8.4) D27(10,8.4) D28(10.8,8.4) E1(-10.8,7.6) E2(-10,7.6) E3(-9.2,7.6) E4(-8.4,7.6) E5(-7.6,7.6) E6(-6.8,7.6) E7(-6,7.6) E8(-5.2,7.6) E9(-4.4,7.6) E10(-3.6,7.6) E11(-2.8,7.6) E12(-2,7.6) E13(-1.2,7.6) E14(-0.4,7.6) E15(0.4,7.6) E16(1.2,7.6) E17(2,7.6) E18(2.8,7.6) E19(3.6,7.6) E20(4.4,7.6) E21(5.2,7.6) E22(6,7.6) E23(6.8,7.6) E24(7.6,7.6) E25(8.4,7.6) E26(9.2,7.6) E27(10,7.6) E28(10.8,7.6) F1(-10.8,6.8) F2(-10,6.8) F3(-9.2,6.8) F4(-8.4,6.8) F5(-7.6,6.8) F6(-6.8,6.8) F7(-6,6.8) F8(-5.2,6.8) F9(-4.4,6.8) F10(-3.6,6.8) F11(-2.8,6.8) F12(-2,6.8) F13(-1.2,6.8) F14(-0.4,6.8) F15(0.4,6.8) F16(1.2,6.8) F17(2,6.8) F18(2.8,6.8) F19(3.6,6.8) F20(4.4,6.8) F21(5.2,6.8) F22(6,6.8) F23(6.8,6.8) F24(7.6,6.8) F25(8.4,6.8) F26(9.2,6.8) F27(10,6.8) F28(10.8,6.8) G1(-10.8,6) G2(-10,6) G4(-8.4,6) G5(-7.6,6) G6(-6.8,6) G7(-6,6) G8(-5.2,6) G9(-4.4,6) G10(-3.6,6) G11(-2.8,6) G12(-2,6) G13(-1.2,6) G14(-0.4,6) G15(0.4,6) G16(1.2,6) G17(2,6) G18(2.8,6) G19(3.6,6) G20(4.4,6) G21(5.2,6) G22(6,6) G23(6.8,6) G24(7.6,6) G25(8.4,6) G26(9.2,6) G27(10,6) G28(10.8,6) H1(-10.8,5.2) H2(-10,5.2) H3(-9.2,5.2) H4(-8.4,5.2) H5(-7.6,5.2) H6(-6.8,5.2) H7(-6,5.2) H8(-5.2,5.2) H9(-4.4,5.2) H10(-3.6,5.2) H11(-2.8,5.2) H12(-2,5.2) H13(-1.2,5.2) H14(-0.4,5.2) H15(0.4,5.2) H16(1.2,5.2) H17(2,5.2) H18(2.8,5.2) H19(3.6,5.2) H20(4.4,5.2) H21(5.2,5.2) H22(6,5.2) H23(6.8,5.2) H24(7.6,5.2) H25(8.4,5.2) H26(9.2,5.2) H27(10,5.2) H28(10.8,5.2) J1(-10.8,4.4) J2(-10,4.4) J3(-9.2,4.4) J4(-8.4,4.4) J5(-7.6,4.4) J6(-6.8,4.4) J7(-6,4.4) J8(-5.2,4.4) J9(-4.4,4.4) J10(-3.6,4.4) J11(-2.8,4.4) J12(-2,4.4) J13(-1.2,4.4) J14(-0.4,4.4) J15(0.4,4.4) J16(1.2,4.4) J17(2,4.4) J18(2.8,4.4) J19(3.6,4.4) J20(4.4,4.4) J21(5.2,4.4) J22(6,4.4) J23(6.8,4.4) J24(7.6,4.4) J25(8.4,4.4) J26(9.2,4.4) J27(10,4.4) J28(10.8,4.4) K1(-10.8,3.6) K2(-10,3.6) K4(-8.4,3.6) K5(-7.6,3.6) K6(-6.8,3.6) K7(-6,3.6) K8(-5.2,3.6) K9(-4.4,3.6) K10(-3.6,3.6) K11(-2.8,3.6) K12(-2,3.6) K13(-1.2,3.6) K14(-0.4,3.6) K15(0.4,3.6) K16(1.2,3.6) K17(2,3.6) K18(2.8,3.6) K19(3.6,3.6) K20(4.4,3.6) K21(5.2,3.6) K22(6,3.6) K23(6.8,3.6) K24(7.6,3.6) K25(8.4,3.6) K27(10,3.6) K28(10.8,3.6) L1(-10.8,2.8) L2(-10,2.8) L3(-9.2,2.8) L4(-8.4,2.8) L5(-7.6,2.8) L6(-6.8,2.8) L7(-6,2.8) L8(-5.2,2.8) L9(-4.4,2.8) L10(-3.6,2.8) L11(-2.8,2.8) L12(-2,2.8) L13(-1.2,2.8) L14(-0.4,2.8) L15(0.4,2.8) L16(1.2,2.8) L17(2,2.8) L18(2.8,2.8) L19(3.6,2.8) L20(4.4,2.8) L21(5.2,2.8) L22(6,2.8) L23(6.8,2.8) L24(7.6,2.8) L25(8.4,2.8) L26(9.2,2.8) L27(10,2.8) L28(10.8,2.8) M1(-10.8,2) M2(-10,2) M3(-9.2,2) M4(-8.4,2) M5(-7.6,2) M6(-6.8,2) M7(-6,2) M8(-5.2,2) M9(-4.4,2) M10(-3.6,2) M11(-2.8,2) M12(-2,2) M13(-1.2,2) M14(-0.4,2) M15(0.4,2) M16(1.2,2) M17(2,2) M18(2.8,2) M19(3.6,2) M20(4.4,2) M21(5.2,2) M22(6,2) M23(6.8,2) M24(7.6,2) M25(8.4,2) M26(9.2,2) M27(10,2) M28(10.8,2) N1(-10.8,1.2) N2(-10,1.2) N4(-8.4,1.2) N5(-7.6,1.2) N6(-6.8,1.2) N7(-6,1.2) N8(-5.2,1.2) N9(-4.4,1.2) N10(-3.6,1.2) N11(-2.8,1.2) N12(-2,1.2) N13(-1.2,1.2) N14(-0.4,1.2) N15(0.4,1.2) N16(1.2,1.2) N17(2,1.2) N18(2.8,1.2) N19(3.6,1.2) N20(4.4,1.2) N21(5.2,1.2) N22(6,1.2) N23(6.8,1.2) N24(7.6,1.2) N25(8.4,1.2) N27(10,1.2) N28(10.8,1.2) P1(-10.8,0.4) P2(-10,0.4) P3(-9.2,0.4) P4(-8.4,0.4) P5(-7.6,0.4) P6(-6.8,0.4) P7(-6,0.4) P8(-5.2,0.4) P9(-4.4,0.4) P10(-3.6,0.4) P11(-2.8,0.4) P12(-2,0.4) P13(-1.2,0.4) P14(-0.4,0.4) P15(0.4,0.4) P16(1.2,0.4) P17(2,0.4) P18(2.8,0.4) P19(3.6,0.4) P20(4.4,0.4) P21(5.2,0.4) P22(6,0.4) P23(6.8,0.4) P24(7.6,0.4) P25(8.4,0.4) P26(9.2,0.4) P27(10,0.4) P28(10.8,0.4) R1(-10.8,-0.4) R2(-10,-0.4) R3(-9.2,-0.4) R4(-8.4,-0.4) R5(-7.6,-0.4) R6(-6.8,-0.4) R7(-6,-0.4) R8(-5.2,-0.4) R9(-4.4,-0.4) R10(-3.6,-0.4) R11(-2.8,-0.4) R12(-2,-0.4) R13(-1.2,-0.4) R14(-0.4,-0.4) R15(0.4,-0.4) R16(1.2,-0.4) R17(2,-0.4) R18(2.8,-0.4) R19(3.6,-0.4) R20(4.4,-0.4) R21(5.2,-0.4) R22(6,-0.4) R23(6.8,-0.4) R24(7.6,-0.4) R25(8.4,-0.4) R26(9.2,-0.4) R27(10,-0.4) R28(10.8,-0.4) T1(-10.8,-1.2) T2(-10,-1.2) T4(-8.4,-1.2) T5(-7.6,-1.2) T6(-6.8,-1.2) T7(-6,-1.2) T8(-5.2,-1.2) T9(-4.4,-1.2) T10(-3.6,-1.2) T11(-2.8,-1.2) T12(-2,-1.2) T13(-1.2,-1.2) T14(-0.4,-1.2) T15(0.4,-1.2) T16(1.2,-1.2) T17(2,-1.2) T18(2.8,-1.2) T19(3.6,-1.2) T20(4.4,-1.2) T21(5.2,-1.2) T22(6,-1.2) T23(6.8,-1.2) T24(7.6,-1.2) T25(8.4,-1.2) T27(10,-1.2) T28(10.8,-1.2) U1(-10.8,-2) U2(-10,-2) U3(-9.2,-2) U4(-8.4,-2) U5(-7.6,-2) U6(-6.8,-2) U7(-6,-2) U8(-5.2,-2) U9(-4.4,-2) U10(-3.6,-2) U11(-2.8,-2) U12(-2,-2) U13(-1.2,-2) U14(-0.4,-2) U15(0.4,-2) U16(1.2,-2) U17(2,-2) U18(2.8,-2) U19(3.6,-2) U20(4.4,-2) U21(5.2,-2) U22(6,-2) U23(6.8,-2) U24(7.6,-2) U25(8.4,-2) U26(9.2,-2) U27(10,-2) U28(10.8,-2) V1(-10.8,-2.8) V2(-10,-2.8) V3(-9.2,-2.8) V4(-8.4,-2.8) V5(-7.6,-2.8) V6(-6.8,-2.8) V7(-6,-2.8) V8(-5.2,-2.8) V9(-4.4,-2.8) V10(-3.6,-2.8) V11(-2.8,-2.8) V12(-2,-2.8) V13(-1.2,-2.8) V14(-0.4,-2.8) V15(0.4,-2.8) V16(1.2,-2.8) V17(2,-2.8) V18(2.8,-2.8) V19(3.6,-2.8) V20(4.4,-2.8) V21(5.2,-2.8) V22(6,-2.8) V23(6.8,-2.8) V24(7.6,-2.8) V25(8.4,-2.8) V26(9.2,-2.8) V27(10,-2.8) V28(10.8,-2.8) W1(-10.8,-3.6) W2(-10,-3.6) W4(-8.4,-3.6) W5(-7.6,-3.6) W6(-6.8,-3.6) W7(-6,-3.6) W8(-5.2,-3.6) W9(-4.4,-3.6) W10(-3.6,-3.6) W11(-2.8,-3.6) W12(-2,-3.6) W13(-1.2,-3.6) W14(-0.4,-3.6) W15(0.4,-3.6) W16(1.2,-3.6) W17(2,-3.6) W18(2.8,-3.6) W19(3.6,-3.6) W20(4.4,-3.6) W21(5.2,-3.6) W22(6,-3.6) W23(6.8,-3.6) W24(7.6,-3.6) W25(8.4,-3.6) W27(10,-3.6) W28(10.8,-3.6) Y1(-10.8,-4.4) Y2(-10,-4.4) Y3(-9.2,-4.4) Y4(-8.4,-4.4) Y5(-7.6,-4.4) Y6(-6.8,-4.4) Y7(-6,-4.4) Y8(-5.2,-4.4) Y9(-4.4,-4.4) Y10(-3.6,-4.4) Y11(-2.8,-4.4) Y12(-2,-4.4) Y13(-1.2,-4.4) Y14(-0.4,-4.4) Y15(0.4,-4.4) Y16(1.2,-4.4) Y17(2,-4.4) Y18(2.8,-4.4) Y19(3.6,-4.4) Y20(4.4,-4.4) Y21(5.2,-4.4) Y22(6,-4.4) Y23(6.8,-4.4) Y24(7.6,-4.4) Y25(8.4,-4.4) Y26(9.2,-4.4) Y27(10,-4.4) Y28(10.8,-4.4)
SM-SO-SC70-5
  rect 0.406x1.016 smd: 1(-0.65,-0.95) 2(0,-0.95) 3(0.65,-0.95) 4(0.65,0.95) 5(-0.65,0.95)
SMINI6-F3-B
  rect 0.305x0.95 smd: 1(0.65,0.75) 2(0,0.75) 3(-0.65,0.75) 4(-0.65,-0.75) 5(0,-0.75) 6(0.65,-0.75)
SO8-25X75
  oval 0.635x1.905 smd: 1(-1.905,-2.794) 2(-0.635,-2.794) 3(0.635,-2.794) 4(1.905,-2.794) 5(1.905,2.794) 6(0.635,2.794) 7(-0.635,2.794) 8(-1.905,2.794)
SOIC_8
  rect 0.61x2.184 smd: 1(-1.905,-2.603)
  oval 0.61x2.184 smd: 2(-0.635,-2.603) 3(0.635,-2.603) 4(1.905,-2.603) 5(1.905,2.603) 6(0.635,2.603) 7(-0.635,2.603) 8(-1.905,2.603)
SOT3_DRT_1P0XP8MM
  rect 0.3x0.3 smd: 1(-0.35,-0.425) 2(0.35,-0.425) 3(0,0.425)
SOT23-3
  rect 1.016x1.016 smd: 1(-1.016,-1.105) 2(1.016,-1.105) 3(0,1.105)
SOT23-5
  rect 0.635x1.27 smd: 1(-0.95,-1.25) 2(0,-1.25) 3(0.95,-1.25) 4(0.95,1.25) 5(-0.95,1.25)
SOT23-6
  rect 0.635x1.016 smd: 1(-0.953,-1.295) 2(0,-1.295) 3(0.953,-1.295) 4(0.953,1.295) 5(0,1.295) 6(-0.953,1.295)
SOT563
  rect 0.3x0.45 smd: 1(-0.5,-0.675) 2(0,-0.675) 3(0.5,-0.675) 4(0.5,0.675) 5(0,0.675) 6(-0.5,0.675)
SOT-23
  rect 1.016x1.016 smd: 1(-1.016,-1.105) 2(1.016,-1.105) 3(0,1.105)
SW4_EVQF004R
  round 1.524 hole 1.016: 1(0,0) 2(4.5,0)
  round 2.286 hole 1.321: 3(-1.25,2.5) 4(5.75,2.5)
TP1-8040
  round 2.032 hole 1.016: 1(0,0)
TP30C12D
  round 0.762 hole 0.305: 1(0,0)
TPD4E05U06DQA
  rect 0.2x0.55 smd: 1(-1,-0.425) 2(-0.5,-0.425) 4(0.5,-0.425) 5(1,-0.425) 6(1,0.425) 7(0.5,0.425) 9(-0.5,0.425) 10(-1,0.425)
  rect 0.4x0.55 smd: 3(0,-0.425) 8(0,0.425)
TQFN28S_3P5X5P5P5
  rect 1.5x2 smd: (0,0)
  rect 0.63x0.28 smd: 1(-1.59,2.25) 2(-1.59,1.75) 3(-1.59,1.25) 4(-1.59,0.75) 5(-1.59,0.25) 6(-1.59,-0.25) 7(-1.59,-0.75) 8(-1.59,-1.25) 9(-1.59,-1.75) 10(-1.59,-2.25) 15(1.59,-2.25) 16(1.59,-1.75) 17(1.59,-1.25) 18(1.59,-0.75) 19(1.59,-0.25) 20(1.59,0.25) 21(1.59,0.75) 22(1.59,1.25) 23(1.59,1.75) 24(1.59,2.25)
  rect 0.28x0.63 smd: 11(-0.75,-2.64) 12(-0.25,-2.64) 13(0.25,-2.64) 14(0.75,-2.64) 25(0.75,2.54) 26(0.25,2.54) 27(-0.25,2.54) 28(-0.75,2.54)
U_5_DRL
  rect 0.3x0.45 smd: 1(-0.5,-0.675) 2(0,-0.675) 3(0.5,-0.675) 4(0.5,0.675) 5(-0.5,0.675)
U_8_DCU
  rect 0.254x1.27 smd: 1(-0.749,-1.473) 2(-0.249,-1.473) 3(0.249,-1.473) 4(0.749,-1.473) 5(0.749,1.473) 6(0.249,1.473) 7(-0.249,1.473) 8(-0.749,1.473)
unnamed#2
  round 3.175 hole 3.175 unplated: (0,0)
unnamed#3
  round 1.016 smd: 1(0,0)
USB5_FCI-10103594
  rect 1.75x0.4 smd: 1(0,1.3) 2(0,0.65) 3(0,0) 4(0,-0.65) 5(0,-1.3)
  oval 1.75x1.2 hole 1.2x0.65: S1(-2.9,2.7) S3(-2.9,-2.7)
  oval 1.5x1.1 hole 1.05x0.65: S2(0.13,2.422) S4(0.13,-2.428)
USB9RA_2SHIELDED
  round 1.27 hole 0.914: 1(0,0) 2(2.5,0) 3(4.5,0) 4(7,0) 5(7.5,1.5) 6(5.5,1.5) 7(3.5,1.5) 8(1.5,1.5) 9(-0.5,1.5)
  round 2.794 hole 2.311: 10(-3.07,-2) 11(10.07,-2)
USB18RA_4SHIELDED
  round 1.27 hole 0.914: 1(0,0) 2(2.5,0) 3(4.5,0) 4(7,0) 5(7.5,1.5) 6(5.5,1.5) 7(3.5,1.5) 8(1.5,1.5) 9(-0.5,1.5) 10(0,3.2) 11(2.5,3.2) 12(4.5,3.2) 13(7,3.2) 14(7.5,4.7) 15(5.5,4.7) 16(3.5,4.7) 17(1.5,4.7) 18(-0.5,4.7)
  oval 2.032x3.048 hole 1.27x2.362: 19(-3.07,-2) 20(10.07,-2) 21(-3.07,3.68) 22(10.07,3.68)
VQFN64S9X9P5
  rect 0.838x0.254 smd: 1(-4.445,3.749) 2(-4.445,3.249) 3(-4.445,2.748) 4(-4.445,2.25) 5(-4.445,1.75) 6(-4.445,1.25) 7(-4.445,0.749) 8(-4.445,0.249) 9(-4.445,-0.249) 10(-4.445,-0.749) 11(-4.445,-1.25) 12(-4.445,-1.75) 13(-4.445,-2.25) 14(-4.445,-2.748) 15(-4.445,-3.249) 16(-4.445,-3.749) 33(4.445,-3.749) 34(4.445,-3.249) 35(4.445,-2.748) 36(4.445,-2.25) 37(4.445,-1.75) 38(4.445,-1.25) 39(4.445,-0.749) 40(4.445,-0.249) 41(4.445,0.249) 42(4.445,0.749) 43(4.445,1.25) 44(4.445,1.75) 45(4.445,2.25) 46(4.445,2.748) 47(4.445,3.249) 48(4.445,3.749)
  rect 0.254x0.838 smd: 17(-3.749,-4.445) 18(-3.249,-4.445) 19(-2.748,-4.445) 20(-2.25,-4.445) 21(-1.75,-4.445) 22(-1.25,-4.445) 23(-0.749,-4.445) 24(-0.249,-4.445) 25(0.249,-4.445) 26(0.749,-4.445) 27(1.25,-4.445) 28(1.75,-4.445) 29(2.25,-4.445) 30(2.748,-4.445) 31(3.249,-4.445) 32(3.749,-4.445) 49(3.749,4.445) 50(3.249,4.445) 51(2.748,4.445) 52(2.25,4.445) 53(1.75,4.445) 54(1.25,4.445) 55(0.749,4.445) 56(0.249,4.445) 57(-0.249,4.445) 58(-0.749,4.445) 59(-1.25,4.445) 60(-1.75,4.445) 61(-2.25,4.445) 62(-2.748,4.445) 63(-3.249,4.445) 64(-3.749,4.445)
  rect 5.994x5.994 smd: 65(0,0)
WSON-8
  rect 0.28x0.5 smd: 1(-0.75,-0.95) 2(-0.25,-0.95) 3(0.25,-0.95) 4(0.75,-0.95) 5(0.75,0.95) 6(0.25,0.95) 7(-0.25,0.95) 8(-0.75,0.95)
  rect 1.6x0.9 smd: 9(0,0)
XTAL2_6X3P5_SMD
  rect 1.905x2.667 smd: 1(-2.146,0) 2(2.146,0)
XTAL4_3P2X2P5_SMD
  rect 1.397x1.143 smd: 1(-1.1,-0.8) 2(1.1,-0.8) 3(1.1,0.8) 4(-1.1,0.8)
XTAL_3P2X5SMD
  rect 1.778x2.286 smd: 1(-1.9,0) 2(1.9,0)
XTAL_CFS-206
  round 1.016 hole 0.66: 1(0,0.762) 2(0,-0.762)

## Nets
3V3_CDC: C428.1 C429.1 C432.1 C434.1 L23.2 U7.9(VDD3) U7.16(VDD4) U7.18(VDD5) U7.20(VDD6)
3V3_RC: C11.2 R12.1
5V0: C17.2 C20.2 C264.1 P3.4 P16.B2 P17.B2 P18.B2 P19.B2 R1.2 R2.1 R215.1 R216.1 R217.1 R218.1 R241.1 R242.2 U2.4(VBIAS) U5.A6(LDO12_IN) U5.A9(LDOUSB_IN2) U5.A10(LDO7USB_IN1) U21.10(VCC_5V)
5V0_COMP: C5.2 R4.1 U1.6(COMP)
5V0_RC: C6.1 R4.2
5V0_SNS: R2.2 R5.2 U1.5(VSNS)
5V0_TAP: C2.1 L1.2 P2.4 R1.1
5V_FAN: C49.1 J1.1 R396.1 U32.3(OUT)
12V: C3.1 C14.1 C402.1 C438.1 C439.1 C440.1 C445.1 F1.2 P16.B1 P17.B1 P18.B1 P19.B1 R3.1 R9.1 R240.1 U1.2(VIN) U3.2(VIN) U28.2(VIN) U32.2(IN)
12V_MAIN: F1.1 P1.1
